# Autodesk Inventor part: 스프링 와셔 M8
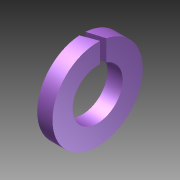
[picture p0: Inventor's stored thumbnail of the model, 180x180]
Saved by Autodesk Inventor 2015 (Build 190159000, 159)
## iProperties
Created: 2024-12
Part Number: 스프링 와셔 M8
Material: 일반
Document SubType Name: Modeling
Designer: 10401
Density: 1 g/cm^3
Appearance: 기본값
Author: 10401
Author: jhkim
Description: 스프링 잠금 와셔
Creation Date: 2024-11-28
Sending System: Autodesk Inventor 2025
Preprocessor: ST-DEVELOPER v20
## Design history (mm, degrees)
node "스프링 와셔 M81"
body "Solid1"
node "기준1"
